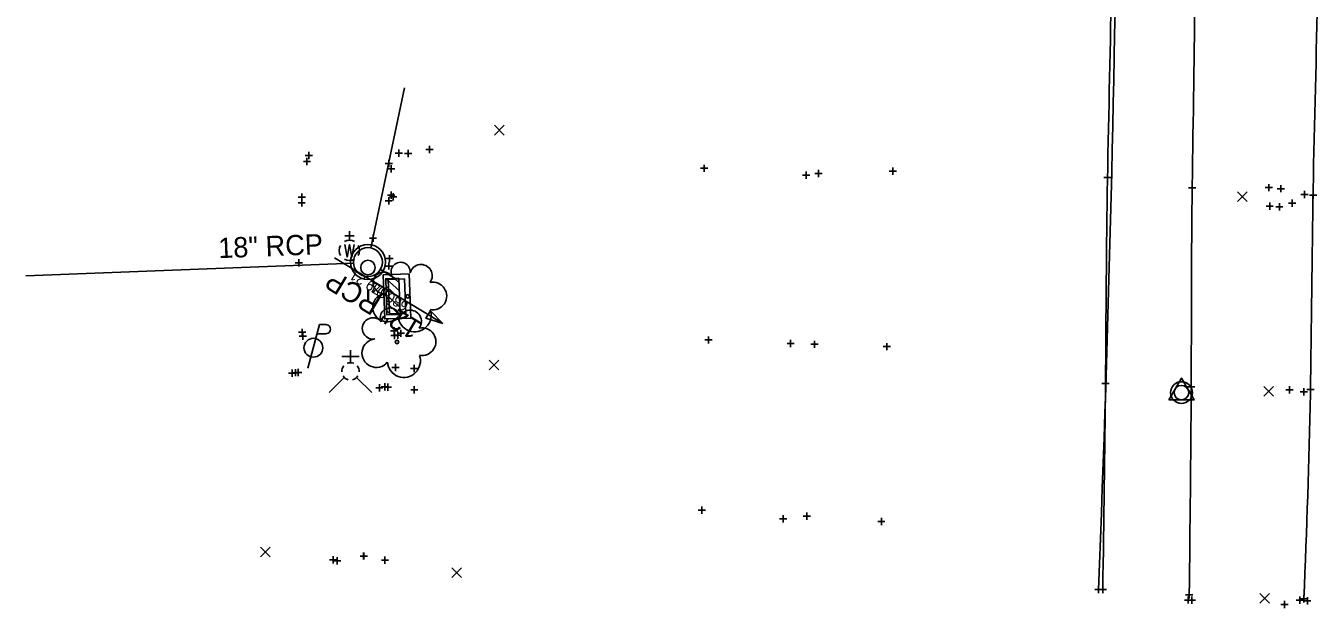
# Model space of a CAD drawing. Extents: x 2188719 to 2189819, y 654569 to 659504.
# Drawn here: x 2189634.1 to 2189812.2, y 657573.1 to 657653.4 of the extents above; entities that cross this region are included whole.
import ezdxf

# ---------------------------------------------------------------- set-up
doc = ezdxf.new("R2010")
doc.units = 0
for name, color, linetype in [('DR_X_Cells', 7, 'Continuous'), ('DR_X_Elev_Flow', 7, 'Continuous'), ('DR_X_Storm_Sewer', 7, 'Continuous'), ('DR_X_Text', 7, 'Continuous'), ('GE_X_Cells', 7, 'Continuous'), ('GK_Drainage_Nodes', 7, 'Continuous'), ('PM_X_Edge_Line', 7, 'Continuous'), ('PV_X_EOP', 7, 'Continuous'), ('PV_X_Shoulder', 7, 'Continuous'), ('SC_Scratch1', 7, 'Continuous'), ('SV_Control_Point', 7, 'Continuous'), ('SV_X_Random_Point', 7, 'Continuous'), ('SV_X_Shot_Marker', 7, 'Continuous'), ('UT_X_Electric_Cells', 7, 'Continuous'), ('UT_X_Water_Cells', 7, 'Continuous'), ('VG_X_Cells', 7, 'Continuous')]:
    doc.layers.add(name, color=color, linetype=linetype)

msp = doc.modelspace()

# ---------------------------------------------------------------- linework, layer by layer
at = {"layer": 'DR_X_Cells'}
for p, q in [((2189683.74, 657618.51), (2189685.56, 657616.82)), ((2189684.88, 657618.55), (2189685.52, 657617.95)), ((2189683.71, 657617.46), (2189685.6, 657615.69)), ((2189683.75, 657616.33), (2189685.64, 657614.56)), ((2189683.78, 657615.2), (2189685.53, 657613.57)), ((2189683.82, 657614.07), (2189684.4, 657613.53))]:
    msp.add_line(p, q, dxfattribs=at)
for points in [[(2189686.9, 657619.17), (2189687.11, 657613.09), (2189683.53, 657612.96), (2189683.32, 657619.04)], [(2189685.5, 657618.58), (2189685.68, 657613.58), (2189683.84, 657613.52), (2189683.67, 657618.51)], [(2189686.26, 657618.48), (2189686.42, 657613.73), (2189684.17, 657613.65), (2189684.01, 657618.4)]]:
    msp.add_lwpolyline(points, close=True, dxfattribs=at)
for centre, radius in [((2189681.22, 657620.8), 2.42), ((2189681.22, 657620.8), 2), ((2189681.22, 657620.05), 1)]:
    msp.add_circle(centre, radius, dxfattribs=at)
at = {"layer": 'DR_X_Elev_Flow'}
for p, q in [((2189681.42, 657624.11), (2189682.42, 657624.11)), ((2189681.92, 657624.61), (2189681.92, 657623.61)), ((2189681.92, 657624.11), (2189681.92, 657624.11)), ((2189684.19, 657621.78), (2189684.19, 657620.78)), ((2189683.69, 657621.28), (2189684.69, 657621.28)), ((2189684.19, 657621.28), (2189684.19, 657621.28))]:
    msp.add_line(p, q, dxfattribs=at)
at = {"layer": 'DR_X_Storm_Sewer'}
for p, q in [((2189681.64, 657622.77), (2189686.27, 657644.84)), ((2189679.26, 657620.66), (2189634.07, 657618.92)), ((2189682.94, 657619.77), (2189685.13, 657618.44))]:
    msp.add_line(p, q, dxfattribs=at)
at = {"layer": 'DR_X_Text'}
msp.add_line((2189676.6, 657621.38), (2189691.56, 657612.33), dxfattribs=at)
msp.add_lwpolyline([(2189691.56, 657612.33), (2189689.2, 657613.06), (2189689.82, 657614.09)], close=True, dxfattribs=at)
at = {"layer": 'GE_X_Cells'}
msp.add_circle((2189793.34, 657602.8), 1.5, dxfattribs=at)
at = {"layer": 'GK_Drainage_Nodes'}
for p, q in [((2189681.22, 657622.8), (2189681.22, 657622.8)), ((2189681.22, 657620.8), (2189681.22, 657620.8)), ((2189681.22, 657620.8), (2189681.22, 657620.8)), ((2189681.22, 657620.05), (2189681.22, 657620.05)), ((2189681.22, 657618.8), (2189681.22, 657618.8)), ((2189685.13, 657618.44), (2189685.13, 657618.44)), ((2189683.42, 657616), (2189683.42, 657616)), ((2189684.09, 657616.03), (2189684.09, 657616.03)), ((2189685.21, 657616.06), (2189685.21, 657616.06)), ((2189685.59, 657616.08), (2189685.59, 657616.08)), ((2189685.59, 657616.08), (2189685.59, 657616.08)), ((2189686.34, 657616.1), (2189686.34, 657616.1)), ((2189687, 657616.13), (2189687, 657616.13)), ((2189685.3, 657613.69), (2189685.3, 657613.69))]:
    msp.add_line(p, q, dxfattribs=at)
msp.add_circle((2189681.22, 657620.8), 2, dxfattribs=at)
at = {"layer": 'PM_X_Edge_Line'}
msp.add_open_spline([(2189715.92, 658416.15), (2189719.55, 658398.42), (2189727.31, 658355.37), (2189741.15, 658285.79), (2189752.08, 658199.49), (2189764.73, 658083.92), (2189776.67, 657949.48), (2189785.57, 657773.05), (2189784.87, 657651.45), (2189781.91, 657575.63)], degree=3, dxfattribs=at)
at = {"layer": 'PV_X_EOP'}
msp.add_open_spline([(2189715.65, 658416.09), (2189717.36, 658407.13), (2189721.67, 658389.5), (2189726.25, 658363.76), (2189732.27, 658338.61), (2189735.95, 658313.21), (2189740.83, 658286.81), (2189744.4, 658258.95), (2189748.43, 658232.12), (2189751.61, 658205.72), (2189755.02, 658180.62), (2189757.39, 658155.27), (2189760.52, 658129.99), (2189762.73, 658103.87), (2189765.52, 658076.79), (2189767.84, 658049.53), (2189770.28, 658023.15), (2189773.03, 657997.24), (2189774.6, 657969.67), (2189777.01, 657941.26), (2189778.8, 657911.99), (2189780.69, 657884.09), (2189781.4, 657856.58), (2189782.11, 657829.65), (2189783.53, 657801.33), (2189783.56, 657772.66), (2189783.96, 657743.23), (2189783.95, 657715.3), (2189783.44, 657687.6), (2189783.88, 657660.21), (2189783.01, 657632.25), (2189782.93, 657604.05), (2189782.64, 657585.12), (2189782.5, 657575.65)], degree=3, dxfattribs=at)
at = {"layer": 'PV_X_Shoulder'}
for points in [[(2189801.82, 658044.25), (2189802.16, 658038.16), (2189802.98, 658023.46), (2189804.8, 657999.54), (2189805.65, 657970.94), (2189806.89, 657942.16), (2189807.79, 657912.49), (2189808.97, 657884.8), (2189810.47, 657856.11), (2189810.57, 657829.12), (2189810.94, 657800.81), (2189811.25, 657772.16), (2189811.38, 657742.5), (2189812.33, 657713.83), (2189811.88, 657686.44), (2189812.29, 657658.62), (2189811.35, 657630.96), (2189811.25, 657602.53), (2189810.6, 657583.97), (2189810.21, 657574.36)], [(2189779.92, 658011.44), (2189780.4, 658006.73), (2189781.74, 657993.22), (2189782.93, 657968.66), (2189785.63, 657948.14), (2189785.75, 657935.25), (2189785.75, 657932.35), (2189787.48, 657924.59), (2189786.45, 657908.18), (2189789.99, 657883.89), (2189789.91, 657856.04), (2189791.07, 657836.67), (2189791.89, 657825.52), (2189792.21, 657822.44), (2189792.71, 657814.94), (2189792.19, 657798.04), (2189794.52, 657772.31), (2189793.99, 657742.26), (2189794.17, 657721.57), (2189794.66, 657709.58), (2189794.51, 657706.15), (2189795.19, 657698.52), (2189794.06, 657682.99), (2189795.47, 657659.17), (2189794.67, 657631.4), (2189794.75, 657603.18), (2189794.52, 657584.46), (2189794.41, 657574.89)]]:
    msp.add_open_spline(points, degree=3, dxfattribs=at)
at = {"layer": 'SV_Control_Point'}
msp.add_line((2189793.34, 657602.8), (2189793.34, 657602.8), dxfattribs=at)
msp.add_lwpolyline([(2189791.6, 657601.8), (2189793.34, 657604.8), (2189795.07, 657601.8)], close=True, dxfattribs=at)
msp.add_circle((2189793.34, 657602.8), 1, dxfattribs=at)
at = {"layer": 'SV_X_Random_Point'}
for p, q in [((2189698.68, 657638.33), (2189700.01, 657639.67)), ((2189698.68, 657639.67), (2189700.01, 657638.33)), ((2189801.06, 657629.17), (2189802.39, 657630.5)), ((2189801.06, 657630.5), (2189802.39, 657629.17)), ((2189697.92, 657605.94), (2189699.25, 657607.27)), ((2189697.92, 657607.27), (2189699.25, 657605.94)), ((2189804.7, 657602.29), (2189806.03, 657603.63)), ((2189804.7, 657603.63), (2189806.03, 657602.29)), ((2189666.4, 657580.17), (2189667.74, 657581.5)), ((2189666.4, 657581.5), (2189667.74, 657580.17)), ((2189692.79, 657577.29), (2189694.12, 657578.63)), ((2189692.79, 657578.63), (2189694.12, 657577.29)), ((2189804.13, 657573.76), (2189805.46, 657575.09)), ((2189804.13, 657575.09), (2189805.46, 657573.76))]:
    msp.add_line(p, q, dxfattribs=at)
at = {"layer": 'SV_X_Shot_Marker'}
for p, q in [((2189673.07, 657635.99), (2189673.07, 657634.99)), ((2189684.96, 657635.84), (2189685.96, 657635.84)), ((2189685.46, 657636.34), (2189685.46, 657635.34)), ((2189685.46, 657635.84), (2189685.46, 657635.84)), ((2189686.78, 657636.29), (2189686.78, 657635.29)), ((2189689.2, 657636.35), (2189690.2, 657636.35)), ((2189689.7, 657636.85), (2189689.7, 657635.85)), ((2189689.7, 657636.35), (2189689.7, 657636.35)), ((2189672.32, 657634.68), (2189673.32, 657634.68)), ((2189672.57, 657635.49), (2189673.57, 657635.49)), ((2189672.82, 657635.18), (2189672.82, 657634.18)), ((2189672.82, 657634.68), (2189672.82, 657634.68)), ((2189673.07, 657635.49), (2189673.07, 657635.49)), ((2189683.6, 657634.39), (2189684.6, 657634.39)), ((2189684.1, 657634.89), (2189684.1, 657633.89)), ((2189684.1, 657634.39), (2189684.1, 657634.39)), ((2189684.42, 657634.17), (2189684.42, 657633.17)), ((2189686.28, 657635.79), (2189687.28, 657635.79)), ((2189686.78, 657635.79), (2189686.78, 657635.79)), ((2189727.57, 657634.24), (2189727.57, 657633.24)), ((2189683.92, 657633.67), (2189684.92, 657633.67)), ((2189684.42, 657633.67), (2189684.42, 657633.67)), ((2189727.07, 657633.74), (2189728.07, 657633.74)), ((2189727.57, 657633.74), (2189727.57, 657633.74)), ((2189741.13, 657632.8), (2189742.13, 657632.8)), ((2189741.63, 657633.3), (2189741.63, 657632.3)), ((2189741.63, 657632.8), (2189741.63, 657632.8)), ((2189742.81, 657633.04), (2189743.81, 657633.04)), ((2189743.31, 657633.54), (2189743.31, 657632.54)), ((2189743.31, 657633.04), (2189743.31, 657633.04)), ((2189753.05, 657633.36), (2189754.05, 657633.36)), ((2189753.55, 657633.86), (2189753.55, 657632.86)), ((2189753.55, 657633.36), (2189753.55, 657633.36)), ((2189782.64, 657632.46), (2189783.64, 657632.46)), ((2189783.14, 657632.96), (2189783.14, 657631.96)), ((2189783.14, 657632.46), (2189783.14, 657632.46)), ((2189684.42, 657630.53), (2189684.42, 657629.53)), ((2189794.31, 657631.05), (2189795.31, 657631.05)), ((2189794.81, 657631.55), (2189794.81, 657630.55)), ((2189794.81, 657631.05), (2189794.81, 657631.05)), ((2189804.88, 657631.07), (2189805.88, 657631.07)), ((2189805.38, 657631.57), (2189805.38, 657630.57)), ((2189805.38, 657631.07), (2189805.38, 657631.07)), ((2189806.55, 657630.93), (2189807.55, 657630.93)), ((2189807.05, 657631.43), (2189807.05, 657630.43)), ((2189807.05, 657630.93), (2189807.05, 657630.93)), ((2189810.3, 657630.63), (2189810.3, 657629.63)), ((2189811.48, 657630.53), (2189811.48, 657629.53)), ((2189671.59, 657628.98), (2189672.59, 657628.98)), ((2189671.6, 657629.78), (2189672.6, 657629.78)), ((2189672.09, 657629.48), (2189672.09, 657628.48)), ((2189672.09, 657628.98), (2189672.09, 657628.98)), ((2189672.1, 657630.28), (2189672.1, 657629.28)), ((2189672.1, 657629.78), (2189672.1, 657629.78)), ((2189683.58, 657629.26), (2189684.58, 657629.26)), ((2189683.92, 657630.03), (2189684.92, 657630.03)), ((2189684.08, 657629.76), (2189684.08, 657628.76)), ((2189684.08, 657629.26), (2189684.08, 657629.26)), ((2189684.2, 657629.79), (2189685.2, 657629.79)), ((2189684.42, 657630.03), (2189684.42, 657630.03)), ((2189684.7, 657630.29), (2189684.7, 657629.29)), ((2189684.7, 657629.79), (2189684.7, 657629.79)), ((2189805.5, 657629.02), (2189805.5, 657628.02)), ((2189806.83, 657628.94), (2189806.83, 657627.94)), ((2189808.11, 657628.93), (2189809.11, 657628.93)), ((2189808.61, 657629.43), (2189808.61, 657628.43)), ((2189808.61, 657628.93), (2189808.61, 657628.93)), ((2189809.8, 657630.13), (2189810.8, 657630.13)), ((2189810.3, 657630.13), (2189810.3, 657630.13)), ((2189810.98, 657630.03), (2189811.98, 657630.03)), ((2189811.48, 657630.03), (2189811.48, 657630.03)), ((2189805, 657628.52), (2189806, 657628.52)), ((2189805.5, 657628.52), (2189805.5, 657628.52)), ((2189806.33, 657628.44), (2189807.33, 657628.44)), ((2189806.83, 657628.44), (2189806.83, 657628.44)), ((2189671.18, 657620.7), (2189672.18, 657620.7)), ((2189671.68, 657621.2), (2189671.68, 657620.2)), ((2189671.68, 657620.7), (2189671.68, 657620.7)), ((2189683.59, 657620.26), (2189684.59, 657620.26)), ((2189684.09, 657620.76), (2189684.09, 657619.76)), ((2189684.09, 657620.26), (2189684.09, 657620.26)), ((2189671.67, 657611.12), (2189672.67, 657611.12)), ((2189672.17, 657611.62), (2189672.17, 657610.62)), ((2189672.17, 657611.12), (2189672.17, 657611.12)), ((2189672.24, 657611.07), (2189672.24, 657610.07)), ((2189684.33, 657611.31), (2189685.33, 657611.31)), ((2189684.83, 657611.81), (2189684.83, 657610.81)), ((2189684.83, 657611.31), (2189684.83, 657611.31)), ((2189684.89, 657611.18), (2189684.89, 657610.18)), ((2189685.26, 657610.98), (2189686.26, 657610.98)), ((2189685.36, 657611.24), (2189685.36, 657610.24)), ((2189685.76, 657611.48), (2189685.76, 657610.48)), ((2189685.76, 657610.98), (2189685.76, 657610.98)), ((2189671.74, 657610.57), (2189672.74, 657610.57)), ((2189672.24, 657610.57), (2189672.24, 657610.57)), ((2189684.39, 657610.68), (2189685.39, 657610.68)), ((2189684.86, 657610.74), (2189685.86, 657610.74)), ((2189684.89, 657610.68), (2189684.89, 657610.68)), ((2189685.36, 657610.74), (2189685.36, 657610.74)), ((2189727.67, 657610.06), (2189728.67, 657610.06)), ((2189728.17, 657610.56), (2189728.17, 657609.56)), ((2189728.17, 657610.06), (2189728.17, 657610.06)), ((2189738.98, 657609.56), (2189739.98, 657609.56)), ((2189739.48, 657610.06), (2189739.48, 657609.06)), ((2189739.48, 657609.56), (2189739.48, 657609.56)), ((2189742.26, 657609.46), (2189743.26, 657609.46)), ((2189742.76, 657609.96), (2189742.76, 657608.96)), ((2189742.76, 657609.46), (2189742.76, 657609.46)), ((2189752.23, 657609.14), (2189753.23, 657609.14)), ((2189752.73, 657609.64), (2189752.73, 657608.64)), ((2189752.73, 657609.14), (2189752.73, 657609.14)), ((2189670.74, 657605.55), (2189671.74, 657605.55)), ((2189670.77, 657605.98), (2189670.77, 657604.98)), ((2189671.1, 657605.56), (2189672.1, 657605.56)), ((2189671.24, 657606.05), (2189671.24, 657605.05)), ((2189671.24, 657605.55), (2189671.24, 657605.55)), ((2189671.6, 657606.06), (2189671.6, 657605.06)), ((2189671.6, 657605.56), (2189671.6, 657605.56)), ((2189684.51, 657606.27), (2189685.51, 657606.27)), ((2189685.01, 657606.77), (2189685.01, 657605.77)), ((2189685.01, 657606.27), (2189685.01, 657606.27)), ((2189687.08, 657606.12), (2189688.08, 657606.12)), ((2189687.58, 657606.62), (2189687.58, 657605.62)), ((2189687.58, 657606.12), (2189687.58, 657606.12)), ((2189670.27, 657605.48), (2189671.27, 657605.48)), ((2189670.77, 657605.48), (2189670.77, 657605.48)), ((2189682.79, 657603.95), (2189682.79, 657602.95)), ((2189683.54, 657604.09), (2189683.54, 657603.09)), ((2189683.54, 657604.09), (2189683.54, 657603.09)), ((2189683.54, 657604.09), (2189683.54, 657603.09)), ((2189683.96, 657604.04), (2189683.96, 657603.04)), ((2189782.37, 657604.06), (2189783.37, 657604.06)), ((2189782.87, 657604.56), (2189782.87, 657603.56)), ((2189782.87, 657604.06), (2189782.87, 657604.06)), ((2189794.68, 657604.09), (2189794.68, 657603.09)), ((2189682.29, 657603.45), (2189683.29, 657603.45)), ((2189682.79, 657603.45), (2189682.79, 657603.45)), ((2189683.04, 657603.59), (2189684.04, 657603.59)), ((2189683.04, 657603.59), (2189684.04, 657603.59)), ((2189683.04, 657603.59), (2189684.04, 657603.59)), ((2189683.46, 657603.54), (2189684.46, 657603.54)), ((2189683.54, 657603.59), (2189683.54, 657603.59)), ((2189683.54, 657603.59), (2189683.54, 657603.59)), ((2189683.54, 657603.59), (2189683.54, 657603.59)), ((2189683.96, 657603.54), (2189683.96, 657603.54)), ((2189687.11, 657603.2), (2189688.11, 657603.2)), ((2189687.61, 657603.7), (2189687.61, 657602.7)), ((2189687.61, 657603.2), (2189687.61, 657603.2)), ((2189794.18, 657603.59), (2189795.18, 657603.59)), ((2189794.68, 657603.59), (2189794.68, 657603.59)), ((2189807.73, 657603.19), (2189808.73, 657603.19)), ((2189808.23, 657603.69), (2189808.23, 657602.69)), ((2189808.23, 657603.19), (2189808.23, 657603.19)), ((2189809.71, 657602.92), (2189810.71, 657602.92)), ((2189810.21, 657603.42), (2189810.21, 657602.42)), ((2189810.21, 657602.92), (2189810.21, 657602.92)), ((2189810.62, 657603.21), (2189811.62, 657603.21)), ((2189811.12, 657603.71), (2189811.12, 657602.71)), ((2189811.12, 657603.21), (2189811.12, 657603.21)), ((2189726.75, 657586.6), (2189727.75, 657586.6)), ((2189727.25, 657587.1), (2189727.25, 657586.1)), ((2189727.25, 657586.6), (2189727.25, 657586.6)), ((2189741.71, 657586.26), (2189741.71, 657585.26)), ((2189737.95, 657585.39), (2189738.95, 657585.39)), ((2189738.45, 657585.89), (2189738.45, 657584.89)), ((2189738.45, 657585.39), (2189738.45, 657585.39)), ((2189741.21, 657585.76), (2189742.21, 657585.76)), ((2189741.71, 657585.76), (2189741.71, 657585.76)), ((2189751.48, 657585.01), (2189752.48, 657585.01)), ((2189751.98, 657585.51), (2189751.98, 657584.51)), ((2189751.98, 657585.01), (2189751.98, 657585.01)), ((2189680.63, 657580.76), (2189680.63, 657579.76)), ((2189680.64, 657580.76), (2189680.64, 657579.76)), ((2189675.93, 657579.73), (2189676.93, 657579.73)), ((2189676.43, 657580.23), (2189676.43, 657579.23)), ((2189676.43, 657579.73), (2189676.43, 657579.73)), ((2189676.49, 657579.59), (2189677.49, 657579.59)), ((2189676.99, 657580.09), (2189676.99, 657579.09)), ((2189676.99, 657579.59), (2189676.99, 657579.59)), ((2189680.13, 657580.26), (2189681.13, 657580.26)), ((2189680.14, 657580.26), (2189681.14, 657580.26)), ((2189680.63, 657580.26), (2189680.63, 657580.26)), ((2189680.64, 657580.26), (2189680.64, 657580.26)), ((2189683.07, 657579.69), (2189684.07, 657579.69)), ((2189683.57, 657580.19), (2189683.57, 657579.19)), ((2189683.57, 657579.69), (2189683.57, 657579.69)), ((2189781.41, 657575.63), (2189782.41, 657575.63)), ((2189781.41, 657575.63), (2189782.41, 657575.63)), ((2189781.41, 657575.63), (2189782.41, 657575.63)), ((2189781.91, 657576.13), (2189781.91, 657575.13)), ((2189781.91, 657576.13), (2189781.91, 657575.13)), ((2189781.91, 657576.13), (2189781.91, 657575.13)), ((2189781.91, 657575.63), (2189781.91, 657575.63)), ((2189781.91, 657575.63), (2189781.91, 657575.63)), ((2189781.91, 657575.63), (2189781.91, 657575.63)), ((2189782, 657575.65), (2189783, 657575.65)), ((2189782, 657575.65), (2189783, 657575.65)), ((2189782.5, 657576.15), (2189782.5, 657575.15)), ((2189782.5, 657576.15), (2189782.5, 657575.15)), ((2189782.5, 657575.65), (2189782.5, 657575.65)), ((2189782.5, 657575.65), (2189782.5, 657575.65)), ((2189794.41, 657575.39), (2189794.41, 657574.39)), ((2189794.41, 657575.39), (2189794.41, 657574.39)), ((2189793.76, 657574.19), (2189794.76, 657574.19)), ((2189793.91, 657574.89), (2189794.91, 657574.89)), ((2189793.91, 657574.89), (2189794.91, 657574.89)), ((2189794.26, 657574.69), (2189794.26, 657573.69)), ((2189794.26, 657574.19), (2189794.26, 657574.19)), ((2189794.27, 657574.17), (2189795.27, 657574.17)), ((2189794.41, 657574.89), (2189794.41, 657574.89)), ((2189794.41, 657574.89), (2189794.41, 657574.89)), ((2189794.77, 657574.67), (2189794.77, 657573.67)), ((2189794.77, 657574.17), (2189794.77, 657574.17)), ((2189807.03, 657573.57), (2189808.03, 657573.57)), ((2189807.53, 657574.07), (2189807.53, 657573.07)), ((2189807.53, 657573.57), (2189807.53, 657573.57)), ((2189809.14, 657574.17), (2189810.14, 657574.17)), ((2189809.64, 657574.67), (2189809.64, 657573.67)), ((2189809.64, 657574.17), (2189809.64, 657574.17)), ((2189809.71, 657574.36), (2189810.71, 657574.36)), ((2189809.71, 657574.36), (2189810.71, 657574.36)), ((2189810.19, 657574.07), (2189811.19, 657574.07)), ((2189810.21, 657574.86), (2189810.21, 657573.86)), ((2189810.21, 657574.86), (2189810.21, 657573.86)), ((2189810.21, 657574.36), (2189810.21, 657574.36)), ((2189810.21, 657574.36), (2189810.21, 657574.36)), ((2189810.69, 657574.57), (2189810.69, 657573.57)), ((2189810.69, 657574.07), (2189810.69, 657574.07))]:
    msp.add_line(p, q, dxfattribs=at)
at = {"layer": 'UT_X_Electric_Cells'}
for p, q in [((2189674.56, 657612.19), (2189672.95, 657606.19)), ((2189674.22, 657610.91), (2189675.41, 657610.91)), ((2189674.56, 657612.19), (2189675.41, 657612.19))]:
    msp.add_line(p, q, dxfattribs=at)
msp.add_circle((2189673.7, 657608.99), 1.3, dxfattribs=at)
msp.add_arc((2189675.42, 657611.55), 0.638, 268.8767, 91.1233, dxfattribs=at)
at = {"layer": 'UT_X_Water_Cells'}
for p, q in [((2189679.31, 657624.44), (2189678.04, 657624.44)), ((2189678.67, 657623.8), (2189678.67, 657625.08)), ((2189678.67, 657622.4), (2189678.67, 657622.4)), ((2189680.01, 657607.79), (2189677.61, 657607.79)), ((2189678.81, 657606.93), (2189678.81, 657608.65)), ((2189678.81, 657605.73), (2189678.81, 657605.73)), ((2189678.81, 657605.73), (2189678.81, 657605.73)), ((2189677.96, 657604.88), (2189675.88, 657602.8)), ((2189679.66, 657604.88), (2189681.74, 657602.8))]:
    msp.add_line(p, q, dxfattribs=at)
msp.add_lwpolyline([(2189678.04, 657623.22), (2189678.35, 657621.5), (2189678.67, 657623.22), (2189678.99, 657621.5), (2189679.31, 657623.22)], dxfattribs=at)
for centre, radius, start, end in [((2189678.67, 657622.41), 1.4, 60.0184, 120.0157), ((2189678.67, 657622.41), 1.4, 150.0184, 209.9816), ((2189678.67, 657622.41), 1.4, 330.0184, 29.9816), ((2189678.67, 657622.41), 1.4, 239.9843, 299.9816), ((2189678.81, 657605.73), 1.2, 140.021, 184.0629), ((2189678.81, 657605.73), 1.2, 68.1395, 112.038), ((2189678.81, 657605.73), 1.2, 356.0165, 39.9889), ((2189678.81, 657605.73), 1.2, 211.8788, 255.8479), ((2189678.81, 657605.73), 1.2, 283.8239, 329.9097)]:
    msp.add_arc(centre, radius, start, end, dxfattribs=at)
at = {"layer": 'VG_X_Cells'}
for centre in [(2189686.7, 657616.09), (2189685.22, 657609.79)]:
    msp.add_circle(centre, 0.24, dxfattribs=at)
for centre, radius, start, end in [((2189685.72, 657619.46), 1.32, 354.0047, 205.9741), ((2189688.53, 657618.92), 1.55, 323.83, 165.0376), ((2189683.39, 657617.95), 1.47, 39.0625, 279.5412), ((2189690.16, 657616.12), 1.91, 259.1453, 101.4596), ((2189683.85, 657614.54), 1.97, 96.1722, 320.5737), ((2189684.24, 657613.16), 1.32, 354.0047, 205.9741), ((2189681.91, 657611.65), 1.47, 39.0625, 279.5412), ((2189687.65, 657613.48), 2.28, 184.9476, 19.4572), ((2189687.05, 657612.62), 1.55, 323.83, 165.0376), ((2189688.68, 657609.83), 1.91, 259.1453, 101.4596), ((2189682.37, 657608.24), 1.97, 96.1722, 320.5737), ((2189686.17, 657607.18), 2.28, 184.9476, 19.4572)]:
    msp.add_arc(centre, radius, start, end, dxfattribs=at)

# ---------------------------------------------------------------- texts
at = {"layer": 'DR_X_Text'}
for s, rotation, p in [('18" RCP', 2.2059, (2189660.63, 657621.34)), ('12" RCP', 148.8491, (2189688.83, 657612.34))]:
    msp.add_text(s, height=2.8, rotation=rotation, dxfattribs=at).set_placement(p)
at = {"layer": 'SC_Scratch1'}
for s, p in [('679.21', (2189684.15, 657616.81)), ('680.01', (2189686.94, 657615.12))]:
    msp.add_text(s, height=1.4, rotation=148.8491, dxfattribs=at).set_placement(p)

doc.saveas('drawing.dxf')
